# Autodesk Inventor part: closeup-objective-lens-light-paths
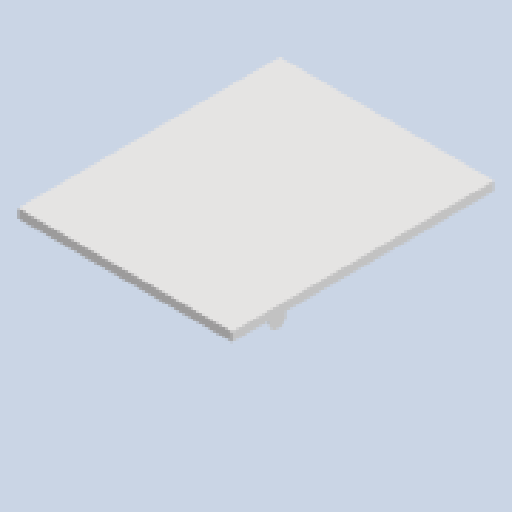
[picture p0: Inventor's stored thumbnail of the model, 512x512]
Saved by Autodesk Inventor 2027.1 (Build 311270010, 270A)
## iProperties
Created: 2026-08
Part Number: closeup-objective-lens-light-paths
Material: Generic
Document SubType Name: Modeling
Designer: dunge
Density: 1 g/cm^3
Appearance: Default
Author: dunge
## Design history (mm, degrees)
sketch "Sketch1"
  geometry: L1 (6.288, -0.362)-(6.288, 5.988) reference; L2 (-9.105, 2.813)-(98.642, 2.813) reference; L3 (6.288, 5.988)-(1.753, 2.813); L4 (1.753, 2.813)-(-2.781, 5.988); L5 (6.288, 5.988)-(-2.781, 5.988); L6 (1.753, 2.813)-(-34.523, 28.214); L7 (-34.523, 28.214)-(-34.523, 2.813); L8 (-9.105, 2.813)-(-34.523, 2.813); 3 further points
  constraints: 14 end point, 2 horizontal, 2 point on line, 1 collinear, 1 equal length, 1 midpoint, 1 perpendicular, 1 vertical, 2 other
  dimensions: "d0" = 55 deg angle of L1 L3
revolve "Revolution1" sketch "Sketch1" stored, may be unused: angle "d1" = 90 deg
sketch "Sketch2"
  geometry: L1 (31.76, -2.813)-(-6.288, -2.813); L2 (-6.288, -2.813)-(-6.288, 0.362); L3 (-6.288, 0.362)-(31.76, 10.557); L4 (31.76, 10.557)-(31.76, -2.813); L5 (9.105, 0.178)-(-98.642, 0.178) reference; L6 (9.105, -2.813)-(-98.642, -2.813) reference; L7 (-6.288, 0.362)-(-6.288, -5.988) reference; 1 further point
  constraints: 12 end point, 3 horizontal, 1 midpoint, 1 parallel, 1 perpendicular, 4 other
  dimensions: "d2" = 105 deg angle of L2 L3
revolve "Revolution2" sketch "Sketch2" stored, may be unused: angle "d3" = 360 deg
workplane "Work Plane1"
sketch "Sketch4"
  geometry: L1 (330.701, -367.832)-(-282.115, -367.832); L2 (-282.115, -367.832)-(-282.115, 381.165); L3 (-282.115, 381.165)-(330.701, 381.165); L4 (330.701, 381.165)-(330.701, -367.832); 1 further point
  constraints: 8 end point, 2 parallel, 1 horizontal, 1 perpendicular
extrude "Extrusion2" new body sketch "Sketch4" distance "d7" = 25.4; taper "d8" = 0 deg
node "red light"
node "Finishes"
node "Reference1"
node "blue light"
node "Reference3"
node "white backing"
node "Finish1" dims "Finish1_Area" = 45899.7332
other parameters: "d6" = 254
